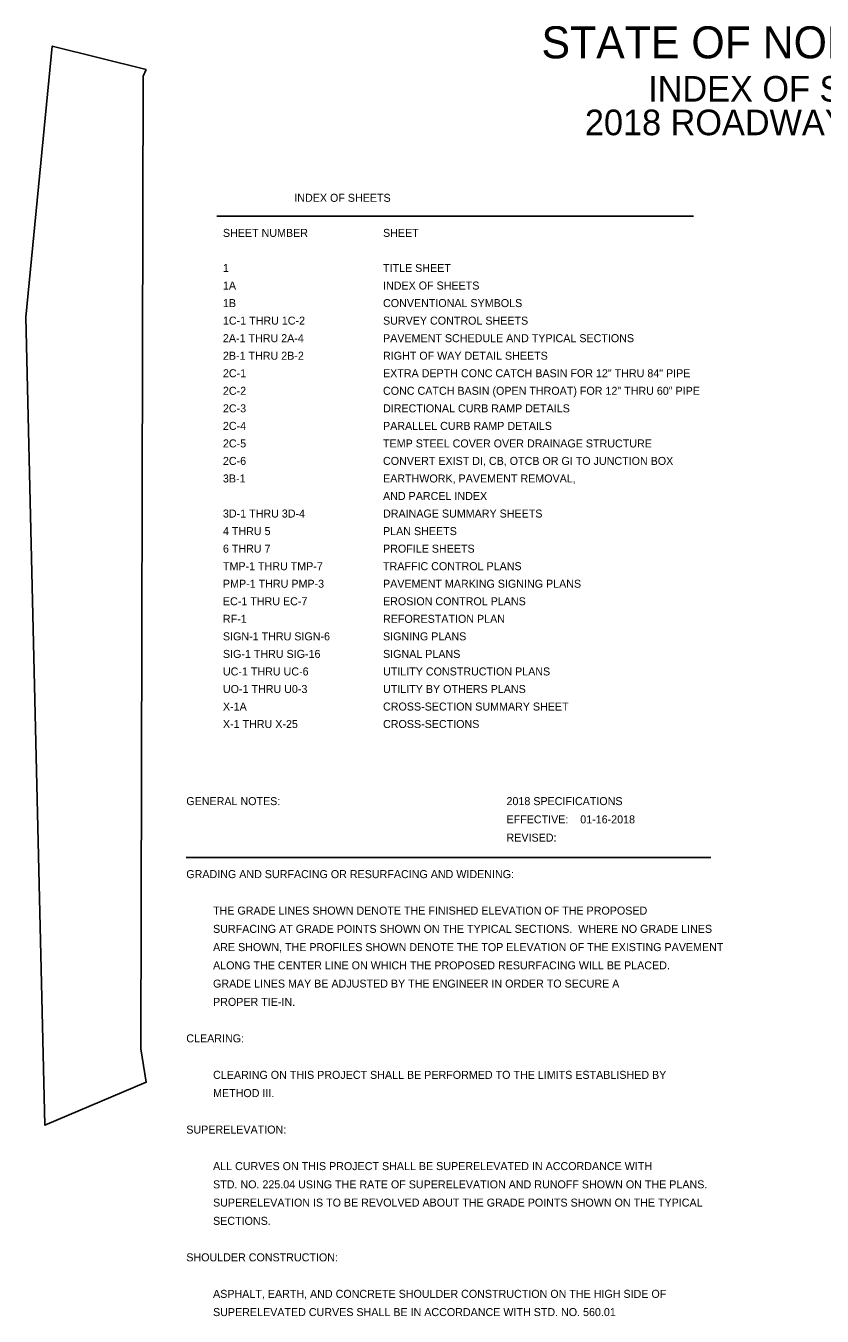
# Model space of a CAD drawing. Extents: x 573079.6 to 573111.5, y -55220.2 to -55200.
# Drawn here: x 573079.63 to 573092.07, y -55220.15 to -55200 of the extents above; entities that cross this region are included whole.
import ezdxf

# ---------------------------------------------------------------- set-up
doc = ezdxf.new("R2010")
doc.units = 0
for name, color, linetype in [('Default', 7, 'Continuous'), ('Scratch_Level_4', 7, 'Continuous'), ('Sheet Data Field CELL', 7, 'Continuous'), ('Sheet Data Text CELL', 7, 'Continuous'), ('Sheet Title CELL', 7, 'Continuous')]:
    doc.layers.add(name, color=color, linetype=linetype)

msp = doc.modelspace()

# ---------------------------------------------------------------- linework, layer by layer
at = {"layer": 'Scratch_Level_4'}
msp.add_lwpolyline([(573081.514, -55200.685), (573080.048, -55200.316), (573079.634, -55204.552), (573079.932, -55217.17), (573081.514, -55216.498), (573081.431, -55215.979), (573081.464, -55200.788)], close=True, dxfattribs=at)
at = {"layer": 'Sheet Data Text CELL'}
for p, q in [((573082.617, -55202.973), (573090.062, -55202.973)), ((573082.14, -55212.987), (573090.333, -55212.987))]:
    msp.add_line(p, q, dxfattribs=at)

# ---------------------------------------------------------------- texts
at = {"layer": 'Default'}
for s, p in [('GENERAL NOTES:                         ', (573082.14, -55212.171)), ('2018 SPECIFICATIONS', (573087.14, -55212.171)), ('EFFECTIVE:    01-16-2018', (573087.14, -55212.456)), ('REVISED:  ', (573087.14, -55212.741)), ('GRADING AND SURFACING OR RESURFACING AND WIDENING:  ', (573082.14, -55213.311)), ('         THE GRADE LINES SHOWN DENOTE THE FINISHED ELEVATION OF THE PROPOSED ', (573082.14, -55213.881)), ('         SURFACING AT GRADE POINTS SHOWN ON THE TYPICAL SECTIONS.  WHERE NO GRADE LINES ', (573082.14, -55214.166)), ('         ARE SHOWN, THE PROFILES SHOWN DENOTE THE TOP ELEVATION OF THE EXISTING PAVEMENT ', (573082.14, -55214.451)), ('         ALONG THE CENTER LINE ON WHICH THE PROPOSED RESURFACING WILL BE PLACED.', (573082.14, -55214.736)), ('         GRADE LINES MAY BE ADJUSTED BY THE ENGINEER IN ORDER TO SECURE A ', (573082.14, -55215.021)), ('         PROPER TIE-IN.  ', (573082.14, -55215.306)), ('CLEARING:  ', (573082.14, -55215.876)), ('         CLEARING ON THIS PROJECT SHALL BE PERFORMED TO THE LIMITS ESTABLISHED BY ', (573082.14, -55216.446)), ('         METHOD III.', (573082.14, -55216.731)), ('SUPERELEVATION:  ', (573082.14, -55217.301)), ('         ALL CURVES ON THIS PROJECT SHALL BE SUPERELEVATED IN ACCORDANCE WITH', (573082.14, -55217.871)), ('         STD. NO. 225.04 USING THE RATE OF SUPERELEVATION AND RUNOFF SHOWN ON THE PLANS.', (573082.14, -55218.156)), ('         SUPERELEVATION IS TO BE REVOLVED ABOUT THE GRADE POINTS SHOWN ON THE TYPICAL ', (573082.14, -55218.441)), ('         SECTIONS.  ', (573082.14, -55218.726)), ('SHOULDER CONSTRUCTION:  ', (573082.14, -55219.296)), ('         ASPHALT, EARTH, AND CONCRETE SHOULDER CONSTRUCTION ON THE HIGH SIDE OF', (573082.14, -55219.866)), ('         SUPERELEVATED CURVES SHALL BE IN ACCORDANCE WITH STD. NO. 560.01', (573082.14, -55220.151))]:
    msp.add_text(s, height=0.125, rotation=360, dxfattribs=at).set_placement(p)
at = {"layer": 'Sheet Data Field CELL'}
for s, p in [('INDEX OF SHEETS, GENERAL NOTES AND', (573089.352, -55201.184)), ('2018 ROADWAY ENGLISH STANDARD DRAWINGS', (573088.364, -55201.709))]:
    msp.add_text(s, height=0.4, dxfattribs=at).set_placement(p)
at = {"layer": 'Sheet Data Text CELL'}
for s, p in [('                        INDEX OF SHEETS ', (573082.712, -55202.749)), ('SHEET NUMBER                    ', (573082.712, -55203.297)), ('SHEET   ', (573085.212, -55203.297)), ('1', (573082.712, -55203.845)), ('TITLE SHEET', (573085.212, -55203.845)), ('1A', (573082.712, -55204.119)), ('INDEX OF SHEETS', (573085.212, -55204.119)), ('1B', (573082.712, -55204.393)), ('CONVENTIONAL SYMBOLS', (573085.212, -55204.393)), ('1C-1 THRU 1C-2', (573082.712, -55204.667)), ('SURVEY CONTROL SHEETS', (573085.212, -55204.667)), ('2A-1 THRU 2A-4', (573082.712, -55204.941)), ('PAVEMENT SCHEDULE AND TYPICAL SECTIONS', (573085.212, -55204.941)), ('2B-1 THRU 2B-2', (573082.712, -55205.215)), ('RIGHT OF WAY DETAIL SHEETS', (573085.212, -55205.215)), ('2C-1  ', (573082.712, -55205.489)), ('EXTRA DEPTH CONC CATCH BASIN FOR 12" THRU 84" PIPE', (573085.212, -55205.489)), ('2C-2', (573082.712, -55205.763)), ('CONC CATCH BASIN (OPEN THROAT) FOR 12" THRU 60" PIPE', (573085.212, -55205.763)), ('2C-3 ', (573082.712, -55206.037)), ('DIRECTIONAL CURB RAMP DETAILS', (573085.212, -55206.037)), ('2C-4', (573082.712, -55206.311)), ('PARALLEL CURB RAMP DETAILS', (573085.212, -55206.311)), ('2C-5', (573082.712, -55206.585)), ('TEMP STEEL COVER OVER DRAINAGE STRUCTURE', (573085.212, -55206.585)), ('2C-6', (573082.712, -55206.858)), ('CONVERT EXIST DI, CB, OTCB OR GI TO JUNCTION BOX', (573085.212, -55206.858)), ('3B-1', (573082.712, -55207.132)), ('EARTHWORK, PAVEMENT REMOVAL, ', (573085.212, -55207.132)), ('AND PARCEL INDEX', (573085.212, -55207.406)), ('3D-1 THRU 3D-4', (573082.712, -55207.68)), ('DRAINAGE SUMMARY SHEETS', (573085.212, -55207.68)), ('4 THRU 5', (573082.712, -55207.954)), ('PLAN SHEETS', (573085.212, -55207.954)), ('6 THRU 7', (573082.712, -55208.228)), ('PROFILE SHEETS', (573085.212, -55208.228)), ('TMP-1 THRU TMP-7', (573082.712, -55208.502)), ('TRAFFIC CONTROL PLANS', (573085.212, -55208.502)), ('PMP-1 THRU PMP-3', (573082.712, -55208.776)), ('PAVEMENT MARKING SIGNING PLANS', (573085.212, -55208.776)), ('EC-1 THRU EC-7', (573082.712, -55209.05)), ('EROSION CONTROL PLANS', (573085.212, -55209.05)), ('RF-1', (573082.712, -55209.324)), ('REFORESTATION PLAN', (573085.212, -55209.324)), ('SIGN-1 THRU SIGN-6', (573082.712, -55209.598)), ('SIGNING PLANS', (573085.212, -55209.598)), ('SIG-1 THRU SIG-16', (573082.712, -55209.872)), ('SIGNAL PLANS', (573085.212, -55209.872)), ('UC-1 THRU UC-6', (573082.712, -55210.146)), ('UTILITY CONSTRUCTION PLANS', (573085.212, -55210.146)), ('UO-1 THRU U0-3', (573082.712, -55210.42)), ('UTILITY BY OTHERS PLANS', (573085.212, -55210.42)), ('X-1A', (573082.712, -55210.694)), ('CROSS-SECTION SUMMARY SHEET', (573085.212, -55210.694)), ('X-1 THRU X-25 ', (573082.712, -55210.967)), ('CROSS-SECTIONS', (573085.212, -55210.967))]:
    msp.add_text(s, height=0.125, dxfattribs=at).set_placement(p)
at = {"layer": 'Sheet Title CELL'}
msp.add_text('STATE OF NORTH CAROLINA DIVISION OF HIGHWAYS', height=0.5, dxfattribs=at).set_placement((573087.686, -55200.508))

doc.saveas('drawing.dxf')
